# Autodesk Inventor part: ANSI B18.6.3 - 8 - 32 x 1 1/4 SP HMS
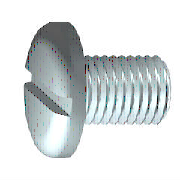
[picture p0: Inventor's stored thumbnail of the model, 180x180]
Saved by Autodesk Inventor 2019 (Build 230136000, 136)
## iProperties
IsCustomPart: 1
Created: 2018-01
Part Number: ANSI B18.6.3 - 8 - 32 x 1 1/4 SP HMS
Material: Steel, Mild
Description: Slotted Pan Head Machine Screw
Document SubType Name: Modeling
Standard: ANSI B18.6.3
Designer: Justin
Standard Revision: 2003
Standards Organization: ANSI
Language: en-US
Size Designation: 8 - 32 x 1 1/4
Categories: <MemberInstance><Categories><Category DisplayName="Fasteners" InternalName="e4da775c-781d-43d5-af7c-5136215cf5a6" Mnemonic="FSTN"><Category DisplayName="Bolts"
Density: 7.85 g/cm^3
Appearance: Semi-Polished
Author: Justin
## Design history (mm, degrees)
body "Solid1"
node "Annotations"
revolve "Body" stored, may be unused: angle "d8" = 90 deg
sketch "Sketch2"
  geometry: L1 (0, 0)-(0, 3.175) reference; L2 (-3.175, 0.686)-(3.175, 0.686); L3 (3.175, 0.686)-(3.175, -0.686); L4 (3.175, -0.686)-(-3.175, -0.686); L5 (-3.175, -0.686)-(-3.175, 0.686); L6 (-3.175, 0)-(3.175, 0); L7 (0, 0.686)-(0, -0.686); C1 r 3.175 at (0, 0) reference; 1 further point
  constraints: 12 end point, 5 midpoint, 2 parallel, 1 collinear, 1 horizontal, 1 perpendicular
  dimensions: "d11" = 1.3716 distance of L4.end L2.start (= SBR); "d12" = 6.35 distance of L2.start L2.end (= KOD)
fillet "Fillet1" dims "d14" = 1.3208 (= RR)
extrude "Slot" cut sketch "Sketch2" distance "d19" = 1.4732 (= STI); taper "d20" = 0 deg
feature "Thread" dims "d15" = 26.9875 (= GEL), "d16" = 0
chamfer "Chamfer1" distance "d17" = 0.39751 (= -0.5 x SPD + 0.5 x GD); stored, may be unused: second distance "d18" = 0.39761 (computed from GUL), angle "d36" = 45 deg
workplane "Work Plane1"
sketch "Sketch1"
  geometry: L1 (-2.438, 0)-(28.702, 0); L2 (28.702, 0)-(28.702, 2.083); L3 (28.702, 2.083)-(1.714, 2.083); L4 (1.714, 2.083)-(1.317, 2.083); L5 (1.317, 2.083)-(0, 2.083); L6 (0, 2.083)-(0, 3.175); L7 (-8.666, 0)-(34.93, 0) reference; L8 (0, -4.445)-(0, 4.445) reference; L9 (-2.438, 0)-(-2.438, 3.175); L10 (0, 3.175)-(-2.438, 3.175); L11 (1.714, 2.083)-(0, 2.083)
  constraints: 18 end point, 4 parallel, 2 collinear, 2 perpendicular, 1 horizontal, 1 point on line
  dimensions: "d0" = 28.702 distance between parallel lines of L2 L6 (= NLG); "d1" = 26.9875 distance from line of L3.end L2 (= GEL); "d2" = 0.39761 distance of L4.end L3.end (computed from GAL); "d3" = 2.4384 distance from line of L1.start L6 (= KOH); "d4" = 4.1656 diameter of L3 L1 (= GD); "d5" = 4.1656 diameter of L5 L1 (= BDM); "d9" = 6.35 diameter of L6.end L1 (= KOD); "d10" = 0 deg angle of L10 L1 (computed from KEWI)
node "Diameter Dimension 1" dims "d0" = 28.702 (= NLG), "d1" = 26.9875 (= GEL), "d2" = 0.39761 (computed from GAL), "d3" = 2.4384 (= KOH), "d4" = 4.1656 (= GD), "d5" = 4.1656 (= BDM), "d9" = 6.35 (= KOD), "d10" = 0 (computed from KEWI), "d11" = 1.3716 (= SBR), "d12" = 6.35 (= KOD), "d45" = 4.1656 (derived)
other parameters: "GD" = 4.1656 (= NND) [user parameter; used in 2 equation terms], "NLG" = 28.702 [user parameter; used in 1 equation term], "GEL" = 26.9875 [user parameter; used in 2 equation terms], "KOD" = 6.35 [user parameter; used in 2 equation terms], "KOH" = 2.4384 [user parameter; used in 1 equation term], "GAL" = 0.39751 [user parameter; used in 1 equation term], "SPD" = 3.37058 (= GD1) [user parameter; used in 1 equation term], "BDM" = 4.1656 (= NND) [user parameter; used in 1 equation term], "GUL" = 0.39751 [user parameter; used in 1 equation term], "RR" = 1.3208 [user parameter; used in 1 equation term], "d7" = 0, "SBR" = 1.3716 [user parameter; used in 1 equation term], "STI" = 1.4732 [user parameter; used in 1 equation term], "KEWI" = 0 [user parameter; used in 1 equation term], "d37" = 0, "d39" = 0, "PTC" = 0.79375 (computed from TPU) [user parameter], "THREADDIA" = 4.1656 [user parameter], "TOA" = 30 deg [user parameter], "NND" = 4.1656 [user parameter; used in 2 equation terms], "GD1" = 3.37058 [user parameter; used in 1 equation term], "d42" = 13.50297 (derived), "d43" = 6.51377 (derived), "d44" = 2.87814 (derived)
